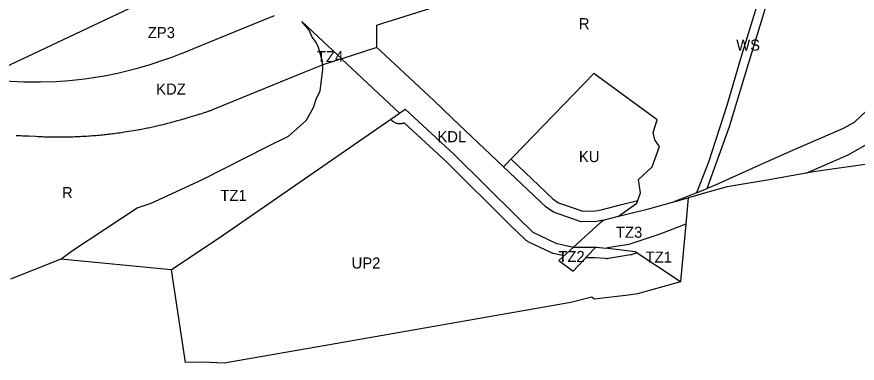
# Model space of a CAD drawing. Extents: x 7435758 to 7439981, y 5550649 to 5554049.
# Drawn here: x 7437843.8 to 7438238.4, y 5550921.2 to 5551083.7 of the extents above; entities that cross this region are included whole.
import ezdxf

# ---------------------------------------------------------------- set-up
doc = ezdxf.new("R2010")
doc.units = 0
for name, color, linetype in [('linie_rozgraniczające', 7, 'Continuous'), ('linie_zabudowy_nieprzekraczalne', 7, 'Continuous'), ('oznaczenia_przeznaczen', 7, 'Continuous')]:
    doc.layers.add(name, color=color, linetype=linetype)

msp = doc.modelspace()

# ---------------------------------------------------------------- linework, layer by layer
at = {"layer": 'linie_rozgraniczające'}
for p, q in [((7437950.17, 5551112.94), (7437826.06, 5551054.35)), ((7438015.73, 5551080.78), (7438126.39, 5551115.61)), ((7438191.67, 5551090.4), (7438183.97, 5551065.05)), ((7438187.24, 5551061.22), (7438195.69, 5551088.86)), ((7437949.85, 5551078.26), (7437964.76, 5551084.36)), ((7437981.12, 5551077.42), (7437977.71, 5551081.51)), ((7437977.71, 5551081.51), (7437987.85, 5551072.05)), ((7437921.16, 5551066.6), (7437949.85, 5551078.26)), ((7437982.57, 5551074.23), (7437981.12, 5551077.42)), ((7438012.78, 5551069.31), (7438012.85, 5551079.88)), ((7438012.85, 5551079.88), (7438015.73, 5551080.78)), ((7437984.11, 5551072.17), (7437982.57, 5551074.23)), ((7437984.79, 5551070.8), (7437984.11, 5551072.17)), ((7437985.48, 5551069.38), (7437984.79, 5551070.8)), ((7437987.34, 5551062.71), (7437985.48, 5551069.38)), ((7437987.85, 5551072.05), (7437996.39, 5551064.1)), ((7438012.78, 5551069.31), (7437996.39, 5551064.1)), ((7438021.28, 5551061.47), (7438012.78, 5551069.31)), ((7437916.27, 5551064.73), (7437921.03, 5551066.55)), ((7437921.03, 5551066.55), (7437921.16, 5551066.6)), ((7437905.9, 5551061.17), (7437914.8, 5551064.17)), ((7437914.8, 5551064.17), (7437916.27, 5551064.73)), ((7437987.4, 5551061.32), (7437987.34, 5551062.71)), ((7437987.34, 5551061.22), (7437987.4, 5551061.32)), ((7437987.48, 5551061.26), (7437987.34, 5551061.22)), ((7437996.34, 5551064.08), (7437987.48, 5551061.26)), ((7437987.57, 5551059.01), (7437987.48, 5551061.26)), ((7437996.39, 5551064.1), (7437996.34, 5551064.08)), ((7437996.34, 5551064.08), (7438023.53, 5551038.53)), ((7438039.6, 5551044.48), (7438021.28, 5551061.47)), ((7438183.97, 5551065.05), (7438177.12, 5551042.19)), ((7437885.74, 5551056.27), (7437891.17, 5551057.35)), ((7437891.17, 5551057.35), (7437899.82, 5551059.46)), ((7437899.82, 5551059.46), (7437905.9, 5551061.17)), ((7437941.89, 5551042.72), (7437978.68, 5551057.7)), ((7437978.68, 5551057.7), (7437987.34, 5551061.22)), ((7437986.19, 5551049.02), (7437987.57, 5551059.01)), ((7438178.46, 5551032.34), (7438187.24, 5551061.22)), ((7437831.37, 5551054.04), (7437847.05, 5551053.17)), ((7437854.93, 5551053.16), (7437862.24, 5551053.42)), ((7437862.24, 5551053.42), (7437868.5, 5551053.89)), ((7437868.5, 5551053.89), (7437875.79, 5551054.69)), ((7437875.79, 5551054.69), (7437885.74, 5551056.27)), ((7438114.74, 5551057.16), (7438072.4, 5551013.34)), ((7438144.52, 5551035.48), (7438114.74, 5551057.16)), ((7437847.05, 5551053.17), (7437854.93, 5551053.16)), ((7437984.43, 5551045.18), (7437986.19, 5551049.02)), ((7437938.24, 5551041.23), (7437941.89, 5551042.72)), ((7437983.16, 5551041.22), (7437984.43, 5551045.18)), ((7438039.61, 5551044.47), (7438039.6, 5551044.48)), ((7438043.42, 5551040.93), (7438039.61, 5551044.47)), ((7438177.12, 5551042.19), (7438168.63, 5551015.58)), ((7438246.13, 5551042.72), (7438236.95, 5551034.22)), ((7437927.37, 5551037.42), (7437928.08, 5551037.64)), ((7437928.08, 5551037.64), (7437929.83, 5551038.18)), ((7437929.83, 5551038.18), (7437930.63, 5551038.43)), ((7437930.63, 5551038.43), (7437931.47, 5551038.7)), ((7437931.47, 5551038.7), (7437931.86, 5551038.82)), ((7437931.86, 5551038.82), (7437932.23, 5551038.94)), ((7437932.23, 5551038.94), (7437932.64, 5551039.08)), ((7437932.64, 5551039.08), (7437933.04, 5551039.21)), ((7437933.04, 5551039.21), (7437933.42, 5551039.34)), ((7437933.42, 5551039.34), (7437933.79, 5551039.47)), ((7437933.79, 5551039.47), (7437934.15, 5551039.6)), ((7437934.15, 5551039.6), (7437934.5, 5551039.73)), ((7437934.5, 5551039.73), (7437934.84, 5551039.86)), ((7437934.84, 5551039.86), (7437935.18, 5551039.98)), ((7437935.18, 5551039.98), (7437935.43, 5551040.07)), ((7437935.18, 5551039.98), (7437935.18, 5551039.98)), ((7437935.43, 5551040.07), (7437938.24, 5551041.23)), ((7437940.79, 5550981.47), (7438023.53, 5551038.53)), ((7437979.64, 5551035.12), (7437983.16, 5551041.22)), ((7438023.53, 5551038.53), (7438026.21, 5551040.38)), ((7438026.21, 5551040.38), (7438049.06, 5551019.31)), ((7438048.46, 5551036.07), (7438043.42, 5551040.93)), ((7437913.67, 5551033.54), (7437914.24, 5551033.68)), ((7437914.24, 5551033.68), (7437914.8, 5551033.83)), ((7437914.8, 5551033.83), (7437915.37, 5551033.97)), ((7437915.37, 5551033.97), (7437915.93, 5551034.12)), ((7437915.93, 5551034.12), (7437916.5, 5551034.26)), ((7437916.5, 5551034.26), (7437917.06, 5551034.41)), ((7437917.06, 5551034.41), (7437917.63, 5551034.56)), ((7437917.63, 5551034.56), (7437918.2, 5551034.72)), ((7437918.2, 5551034.72), (7437918.76, 5551034.87)), ((7437918.76, 5551034.87), (7437919.33, 5551035.03)), ((7437919.33, 5551035.03), (7437919.9, 5551035.18)), ((7437919.9, 5551035.18), (7437920.72, 5551035.42)), ((7437920.72, 5551035.42), (7437921.56, 5551035.66)), ((7437921.56, 5551035.66), (7437922.43, 5551035.91)), ((7437922.43, 5551035.91), (7437923.32, 5551036.18)), ((7437923.32, 5551036.18), (7437924.25, 5551036.46)), ((7437924.25, 5551036.46), (7437925.22, 5551036.75)), ((7437925.22, 5551036.75), (7437926.25, 5551037.07)), ((7437926.25, 5551037.07), (7437927.37, 5551037.42)), ((7437971.46, 5551027.77), (7437979.64, 5551035.12)), ((7438072.4, 5551013.34), (7438048.46, 5551036.07)), ((7438142.66, 5551029.39), (7438144.52, 5551035.48)), ((7438236.95, 5551034.22), (7438231.47, 5551031.2)), ((7437893.17, 5551029.54), (7437894.29, 5551029.71)), ((7437894.29, 5551029.71), (7437895.37, 5551029.87)), ((7437895.37, 5551029.87), (7437896.43, 5551030.04)), ((7437896.43, 5551030.04), (7437897.47, 5551030.2)), ((7437897.47, 5551030.2), (7437898.48, 5551030.37)), ((7437898.48, 5551030.37), (7437899.48, 5551030.54)), ((7437899.48, 5551030.54), (7437900.45, 5551030.72)), ((7437900.45, 5551030.72), (7437901.1, 5551030.83)), ((7437901.1, 5551030.83), (7437901.75, 5551030.95)), ((7437901.75, 5551030.95), (7437902.4, 5551031.08)), ((7437902.4, 5551031.08), (7437903.04, 5551031.2)), ((7437903.04, 5551031.2), (7437903.69, 5551031.33)), ((7437903.69, 5551031.33), (7437904.34, 5551031.46)), ((7437904.34, 5551031.46), (7437904.99, 5551031.59)), ((7437904.99, 5551031.59), (7437905.64, 5551031.72)), ((7437905.64, 5551031.72), (7437906.29, 5551031.86)), ((7437906.29, 5551031.86), (7437906.95, 5551031.99)), ((7437906.95, 5551031.99), (7437907.6, 5551032.13)), ((7437907.6, 5551032.13), (7437908.25, 5551032.28)), ((7437908.25, 5551032.28), (7437908.9, 5551032.42)), ((7437908.9, 5551032.42), (7437909.55, 5551032.57)), ((7437909.55, 5551032.57), (7437910.2, 5551032.71)), ((7437910.2, 5551032.71), (7437910.86, 5551032.87)), ((7437910.86, 5551032.87), (7437911.42, 5551033)), ((7437911.42, 5551033), (7437911.98, 5551033.13)), ((7437911.98, 5551033.13), (7437912.54, 5551033.27)), ((7437912.54, 5551033.27), (7437913.11, 5551033.4)), ((7437913.11, 5551033.4), (7437913.67, 5551033.54)), ((7438167.92, 5551003.15), (7438178.46, 5551032.34)), ((7438231.47, 5551031.2), (7438209.46, 5551021.62)), ((7437843.49, 5551028.11), (7437844.33, 5551028.07)), ((7437844.33, 5551028.07), (7437844.51, 5551028.06)), ((7437844.51, 5551028.06), (7437845.4, 5551028.02)), ((7437845.4, 5551028.02), (7437845.53, 5551028.01)), ((7437845.53, 5551028.01), (7437846.47, 5551027.97)), ((7437846.47, 5551027.97), (7437846.53, 5551027.97)), ((7437846.53, 5551027.97), (7437847.53, 5551027.92)), ((7437847.53, 5551027.92), (7437848.4, 5551027.88)), ((7437848.4, 5551027.88), (7437849.37, 5551027.84)), ((7437849.37, 5551027.84), (7437852.59, 5551027.68)), ((7437852.59, 5551027.68), (7437853.78, 5551027.62)), ((7437853.78, 5551027.62), (7437854.96, 5551027.56)), ((7437854.96, 5551027.56), (7437856.02, 5551027.52)), ((7437856.02, 5551027.52), (7437856.67, 5551027.49)), ((7437856.67, 5551027.49), (7437857.29, 5551027.47)), ((7437857.29, 5551027.47), (7437857.9, 5551027.45)), ((7437857.9, 5551027.45), (7437858.48, 5551027.43)), ((7437858.48, 5551027.43), (7437859.05, 5551027.42)), ((7437859.05, 5551027.42), (7437859.61, 5551027.41)), ((7437859.61, 5551027.41), (7437860.16, 5551027.4)), ((7437860.16, 5551027.4), (7437860.69, 5551027.39)), ((7437860.69, 5551027.39), (7437861.57, 5551027.38)), ((7437861.57, 5551027.38), (7437862.43, 5551027.38)), ((7437862.43, 5551027.38), (7437863.27, 5551027.37)), ((7437863.27, 5551027.37), (7437864.1, 5551027.37)), ((7437864.1, 5551027.37), (7437864.91, 5551027.37)), ((7437864.91, 5551027.37), (7437865.7, 5551027.38)), ((7437865.7, 5551027.38), (7437866.48, 5551027.39)), ((7437866.48, 5551027.39), (7437867.25, 5551027.4)), ((7437867.25, 5551027.4), (7437868.01, 5551027.42)), ((7437868.01, 5551027.42), (7437868.78, 5551027.44)), ((7437868.78, 5551027.44), (7437869.55, 5551027.46)), ((7437869.55, 5551027.46), (7437870.32, 5551027.49)), ((7437870.32, 5551027.49), (7437871.11, 5551027.52)), ((7437871.11, 5551027.52), (7437871.89, 5551027.55)), ((7437871.89, 5551027.55), (7437872.69, 5551027.58)), ((7437872.69, 5551027.58), (7437873.49, 5551027.62)), ((7437873.49, 5551027.62), (7437874.29, 5551027.67)), ((7437874.29, 5551027.67), (7437875.11, 5551027.71)), ((7437875.11, 5551027.71), (7437875.93, 5551027.76)), ((7437875.93, 5551027.76), (7437876.75, 5551027.82)), ((7437876.75, 5551027.82), (7437877.59, 5551027.87)), ((7437877.59, 5551027.87), (7437878.43, 5551027.93)), ((7437878.43, 5551027.93), (7437879.28, 5551028)), ((7437879.28, 5551028), (7437880.14, 5551028.06)), ((7437880.14, 5551028.06), (7437881.04, 5551028.13)), ((7437881.04, 5551028.13), (7437881.88, 5551028.2)), ((7437881.88, 5551028.2), (7437882.67, 5551028.27)), ((7437882.67, 5551028.27), (7437883.43, 5551028.34)), ((7437883.43, 5551028.34), (7437884.16, 5551028.41)), ((7437884.16, 5551028.41), (7437884.87, 5551028.48)), ((7437884.87, 5551028.48), (7437885.56, 5551028.55)), ((7437885.56, 5551028.55), (7437886.23, 5551028.63)), ((7437886.23, 5551028.63), (7437886.85, 5551028.7)), ((7437886.85, 5551028.7), (7437887.49, 5551028.78)), ((7437887.49, 5551028.78), (7437888.15, 5551028.86)), ((7437888.15, 5551028.86), (7437888.84, 5551028.94)), ((7437888.84, 5551028.94), (7437889.55, 5551029.04)), ((7437889.55, 5551029.04), (7437890.31, 5551029.14)), ((7437890.31, 5551029.14), (7437891.11, 5551029.25)), ((7437891.11, 5551029.25), (7437892.01, 5551029.38)), ((7437892.01, 5551029.38), (7437893.17, 5551029.54)), ((7437961.56, 5551022.93), (7437971.46, 5551027.77)), ((7438143.4, 5551026.1), (7438142.66, 5551029.39)), ((7438145.64, 5551022.88), (7438143.4, 5551026.1)), ((7437931.05, 5551007.4), (7437961.56, 5551022.93)), ((7438142.11, 5551013.4), (7438145.64, 5551022.88)), ((7438234.21, 5551018.98), (7438244.34, 5551024.72)), ((7438049.06, 5551019.31), (7438078.83, 5550989.71)), ((7438209.46, 5551021.62), (7438194.33, 5551014.85)), ((7438214.48, 5551010.41), (7438234.21, 5551018.98)), ((7438285.51, 5551020.71), (7438217.88, 5551011.01)), ((7438168.63, 5551015.58), (7438163.02, 5551001.19)), ((7438194.33, 5551014.85), (7438171.36, 5551004.53)), ((7438092.36, 5550994.39), (7438072.4, 5551013.34)), ((7438135.72, 5551007.43), (7438142.11, 5551013.4)), ((7438214.48, 5551010.41), (7438196.16, 5551007.16)), ((7438217.88, 5551011.01), (7438214.48, 5551010.41)), ((7437906.91, 5550996.36), (7437931.05, 5551007.4)), ((7438136.58, 5551001.14), (7438135.72, 5551007.43)), ((7438196.16, 5551007.16), (7438182.92, 5551004.92)), ((7438163.02, 5551001.19), (7438167.92, 5551003.15)), ((7438177.28, 5551003.94), (7438167.18, 5551001.11)), ((7438171.36, 5551004.53), (7438167.92, 5551003.15)), ((7438182.92, 5551004.92), (7438177.28, 5551003.94)), ((7438134.97, 5550996.25), (7438136.58, 5551001.14)), ((7438152.38, 5550996.97), (7438159.06, 5550998.84)), ((7438163.02, 5551001.19), (7438154.27, 5550997.68)), ((7438159.01, 5550998.82), (7438157.91, 5550986.48)), ((7438159.07, 5550998.83), (7438159.01, 5550998.82)), ((7438159.06, 5550998.84), (7438159.07, 5550998.83)), ((7438162.48, 5550999.79), (7438159.07, 5550998.84)), ((7438159.07, 5550998.84), (7438159.07, 5550998.83)), ((7438167.18, 5551001.11), (7438162.48, 5550999.79)), ((7437900.31, 5550994.1), (7437906.91, 5550996.36)), ((7438095.85, 5550992.03), (7438092.36, 5550994.39)), ((7438126.34, 5550990.14), (7438134.97, 5550996.25)), ((7438141.11, 5550993.81), (7438151.65, 5550996.74)), ((7438151.65, 5550996.74), (7438152.32, 5550996.98)), ((7438154.27, 5550997.68), (7438152.32, 5550996.98)), ((7438152.32, 5550996.98), (7438152.38, 5550996.97)), ((7437870.01, 5550974.14), (7437900.31, 5550994.1)), ((7438108.8, 5550987.63), (7438095.85, 5550992.03)), ((7438126.34, 5550990.14), (7438128.33, 5550990.64)), ((7438128.33, 5550990.64), (7438141.11, 5550993.81)), ((7438078.83, 5550989.71), (7438086.12, 5550982.73)), ((7438105.15, 5550975.61), (7438117.93, 5550987.24)), ((7438116.04, 5550987.74), (7438108.8, 5550987.63)), ((7438119.11, 5550988.35), (7438116.04, 5550987.74)), ((7438117.93, 5550987.24), (7438119.15, 5550988.34)), ((7438119.15, 5550988.34), (7438119.11, 5550988.35)), ((7438119.15, 5550988.35), (7438126.34, 5550990.14)), ((7438119.15, 5550988.34), (7438119.15, 5550988.35)), ((7438157.91, 5550986.48), (7438145.81, 5550981.79)), ((7438157.91, 5550986.48), (7438155.51, 5550959.61)), ((7438086.12, 5550982.73), (7438096.97, 5550977.57)), ((7437916.28, 5550965.08), (7437940.79, 5550981.47)), ((7438145.81, 5550981.79), (7438131.16, 5550976.99)), ((7438096.97, 5550977.57), (7438105.15, 5550975.61)), ((7438105.15, 5550975.61), (7438098.28, 5550969.37)), ((7438104.97, 5550964.34), (7438114.92, 5550974.82)), ((7438105.15, 5550975.61), (7438115.8, 5550975.74)), ((7438114.92, 5550974.82), (7438115.76, 5550975.7)), ((7438115.8, 5550975.74), (7438115.76, 5550975.71)), ((7438115.76, 5550975.71), (7438115.76, 5550975.7)), ((7438115.76, 5550975.7), (7438120.74, 5550975.26)), ((7438120.74, 5550975.26), (7438121.15, 5550975.33)), ((7438124.21, 5550975.84), (7438121.15, 5550975.33)), ((7438121.15, 5550975.33), (7438121.34, 5550975.24)), ((7438121.34, 5550975.24), (7438134.15, 5550973.59)), ((7438131.16, 5550976.99), (7438124.21, 5550975.84)), ((7437864.55, 5550970.01), (7437870.01, 5550974.14)), ((7438134.15, 5550973.59), (7438155.51, 5550959.61)), ((7437864.51, 5550969.99), (7437840.8, 5550960.67)), ((7437864.55, 5550969.99), (7437864.51, 5550969.99)), ((7437864.55, 5550969.99), (7437864.55, 5550970.01)), ((7437916.28, 5550965.08), (7437864.55, 5550969.99)), ((7438098.28, 5550969.37), (7438104.97, 5550964.34)), ((7437916.46, 5550965.07), (7437916.28, 5550965.08)), ((7437922.95, 5550921.62), (7437916.46, 5550965.07)), ((7438155.5, 5550959.44), (7438135.18, 5550953.79)), ((7438155.51, 5550959.61), (7438155.5, 5550959.44)), ((7438113.81, 5550952.18), (7438103.91, 5550949.67)), ((7438114.95, 5550951.32), (7438113.81, 5550952.18)), ((7438131.01, 5550953.22), (7438114.95, 5550951.32)), ((7438135.18, 5550953.79), (7438131.01, 5550953.22)), ((7438103.91, 5550949.67), (7437990.62, 5550929.87)), ((7437990.62, 5550929.87), (7437941.14, 5550921.25)), ((7437930.91, 5550921.66), (7437922.95, 5550921.62)), ((7437941.14, 5550921.25), (7437930.91, 5550921.66))]:
    msp.add_line(p, q, dxfattribs=at)
at = {"layer": 'linie_zabudowy_nieprzekraczalne'}
for points in [[(7438100.67, 5550971.54), (7438095.81, 5550972.7), (7438095.56, 5550972.77), (7438095.25, 5550972.87), (7438094.94, 5550973), (7438094.82, 5550973.05), (7438083.97, 5550978.21), (7438083.8, 5550978.3), (7438083.51, 5550978.46), (7438083.24, 5550978.64), (7438082.98, 5550978.84), (7438082.73, 5550979.05), (7438082.66, 5550979.12), (7438075.37, 5550986.11), (7438075.31, 5550986.17), (7438045.6, 5551015.7), (7438025.72, 5551034.04), (7438025.63, 5551033.99), (7438025.32, 5551033.87), (7438025.01, 5551033.76), (7438024.7, 5551033.67), (7438024.38, 5551033.6), (7438024.06, 5551033.56), (7438023.73, 5551033.54), (7438023.4, 5551033.53), (7438023.08, 5551033.55), (7438022.75, 5551033.59), (7438022.43, 5551033.65), (7438022.11, 5551033.74), (7438021.8, 5551033.84), (7438021.5, 5551033.96), (7438021.2, 5551034.1), (7438020.92, 5551034.26), (7438020.65, 5551034.44), (7438020.38, 5551034.64), (7438020.14, 5551034.86), (7438020.1, 5551034.89), (7438019.31, 5551035.63)], [(7438075.88, 5551016.94), (7438095.51, 5550998.3), (7438098.09, 5550996.55), (7438109.59, 5550992.64), (7438115.51, 5550992.73), (7438118.14, 5550993.25), (7438127.12, 5550995.49), (7438127.13, 5550995.5), (7438135.37, 5550997.54)], [(7438135.22, 5550973.06), (7438132.72, 5550972.24), (7438132.65, 5550972.22), (7438132.34, 5550972.13), (7438132.02, 5550972.07), (7438131.98, 5550972.06), (7438121.6, 5550970.33), (7438121.57, 5550970.33), (7438121.27, 5550970.29), (7438120.95, 5550970.26), (7438120.62, 5550970.26), (7438120.3, 5550970.28), (7438120.29, 5550970.28), (7438115.32, 5550970.72), (7438115.31, 5550970.72), (7438115.23, 5550970.73), (7438110.84, 5550970.68)]]:
    msp.add_lwpolyline(points, dxfattribs=at)

# ---------------------------------------------------------------- texts
at = {"layer": 'oznaczenia_przeznaczen'}
for s, p in [('R', (7438107.72, 5551077.91)), ('ZP3', (7437905.3, 5551073.77)), ('WS', (7438181.58, 5551067.89)), ('TZ4', (7437984.74, 5551062.47)), ('KDZ', (7437909.23, 5551047.24)), ('KDL', (7438041.29, 5551024.91)), ('KU', (7438107.75, 5551015.58)), ('R', (7437865.02, 5550998.68)), ('TZ1', (7437939.37, 5550997.36)), ('TZ3', (7438125.13, 5550980.1)), ('UP2', (7438001.02, 5550965.63)), ('TZ2', (7438098.07, 5550968.69)), ('TZ1', (7438139.05, 5550968.43))]:
    msp.add_text(s, height=5.2, dxfattribs=at).set_placement(p)

doc.saveas('drawing.dxf')
